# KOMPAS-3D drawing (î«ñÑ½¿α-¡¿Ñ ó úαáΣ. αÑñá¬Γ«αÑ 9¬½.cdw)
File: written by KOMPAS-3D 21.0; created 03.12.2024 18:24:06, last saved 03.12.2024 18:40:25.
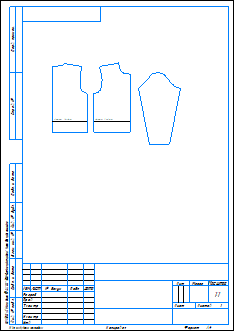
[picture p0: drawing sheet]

Sheet 1: A4, portrait

Document properties: Автор: Admin; Полное имя файла: C:\Users\Admin\Desktop\77\8-9 класс.cdw

Title block, sheet 1: scale: 1:1; Количество листов документа: 1; Форматы листов документа: A4

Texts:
  ЛИНИЯ ТАЛИИ
  Lucida Console
Dimensions and other numbers on the sheet: 1:1; 1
